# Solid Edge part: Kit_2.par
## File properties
Sűrűség: 0,000 kg/m^3
Pontosság: 0,990
Author: ahadarics
Last saved by: ahadarics
Revision: 76
Username: ahadarics
Dokumentum tartalom típus: 0
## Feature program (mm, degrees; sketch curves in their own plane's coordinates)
base feature "unnamed BaseFeature 1"
sketch for "Furat_1" plane through (0, 0, 7.75) normal (0, 0, 1) x-axis (-1, 0, 0)
  hole centre (0, 0) bore radius 4.283
hole "Furat_1" nominal diameter 9.728 finite  ThreadDepth = 7.5 mm
chamfer "Letörés_1" setback 0.7
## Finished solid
Body 1: solid body, 17 faces, 17 edges, 0 vertices.
  Faces by surface: cylinder 7, cone 5, plane 5
  Edges by curve: circle 17
Bounding box of the edges (mm): 27.000 x 27.000 x 23.000, from (-13.5, -13.5, -15.25) to (13.5, 13.5, 7.75).
Cylindrical faces by radius (mm): R0.85 x1, R4.28 x1, R4.283 x1, R8.95 x1, R10 x1, R11.1 x1, R13.5 x1
Conical faces (half-angle, radius in mm at the cone's reference point): 30 deg R9.9134 x1, 45 deg R4.983 x1, 45 deg R9.475 x1, 45 deg R13.25 x1, 59 deg R2.1415 x1
Planar faces by outward normal: +z 2, -z 3
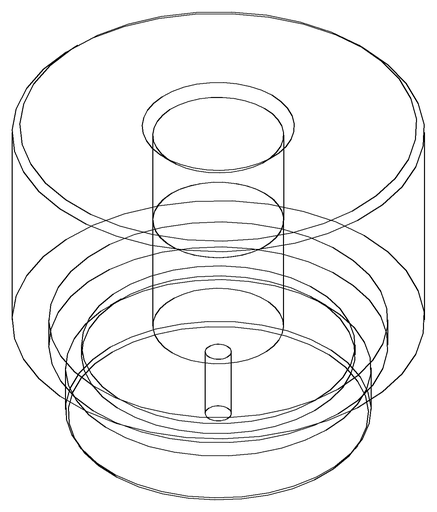
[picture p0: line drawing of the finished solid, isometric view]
